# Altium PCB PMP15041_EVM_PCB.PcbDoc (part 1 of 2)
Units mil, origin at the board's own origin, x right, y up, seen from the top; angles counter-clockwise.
Board outline 2200 x 2100 mil, 4 copper layers (Top Layer, Signal Layer 1, Signal Layer 2, Bottom Layer), stack 60 mil thick; 124 components, 58 nets, 320 pads, 164 vias.
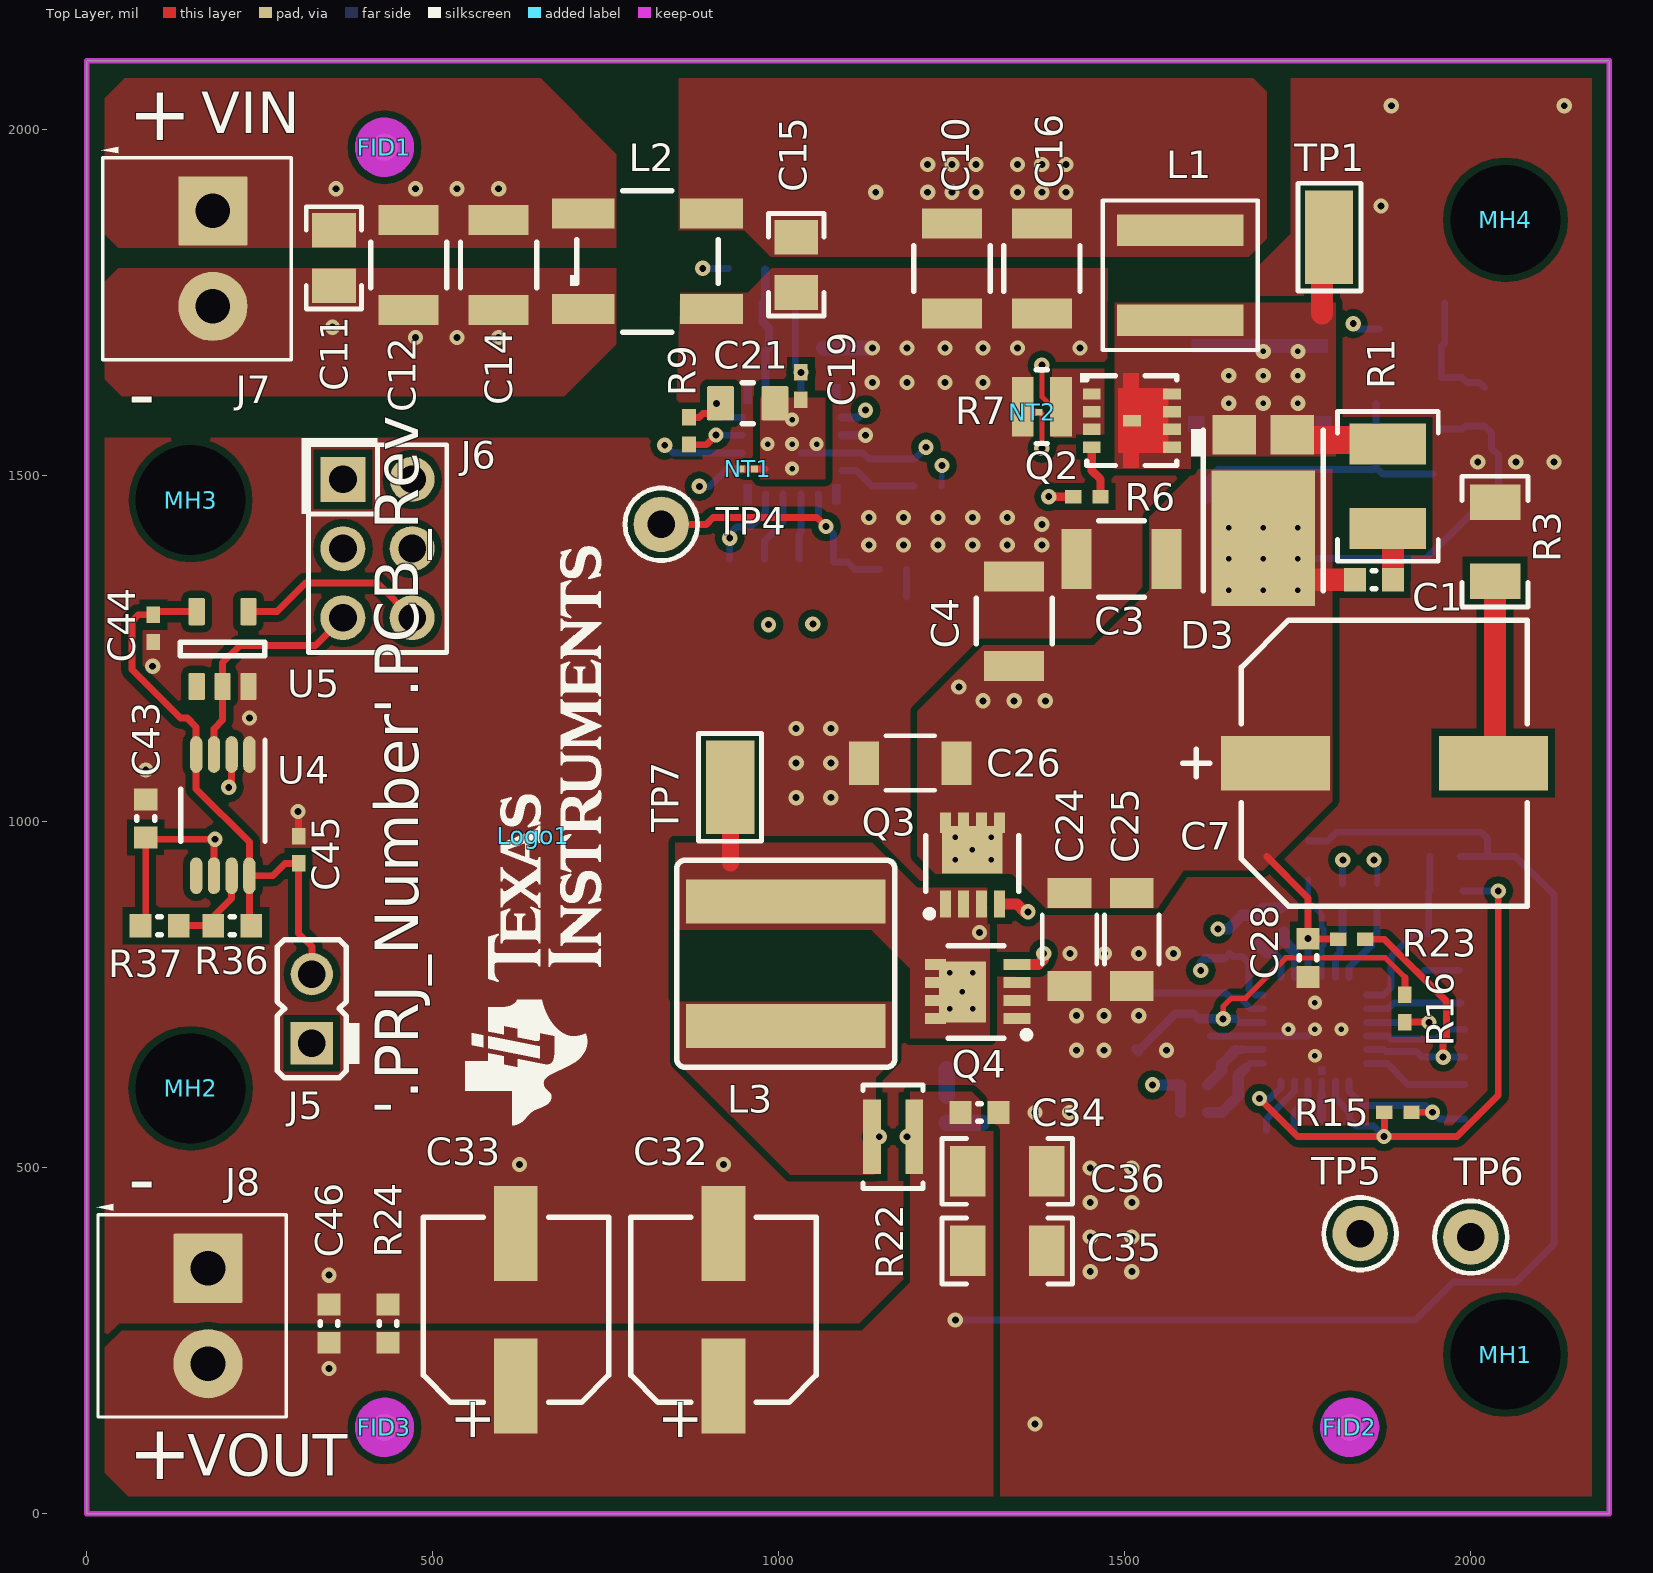
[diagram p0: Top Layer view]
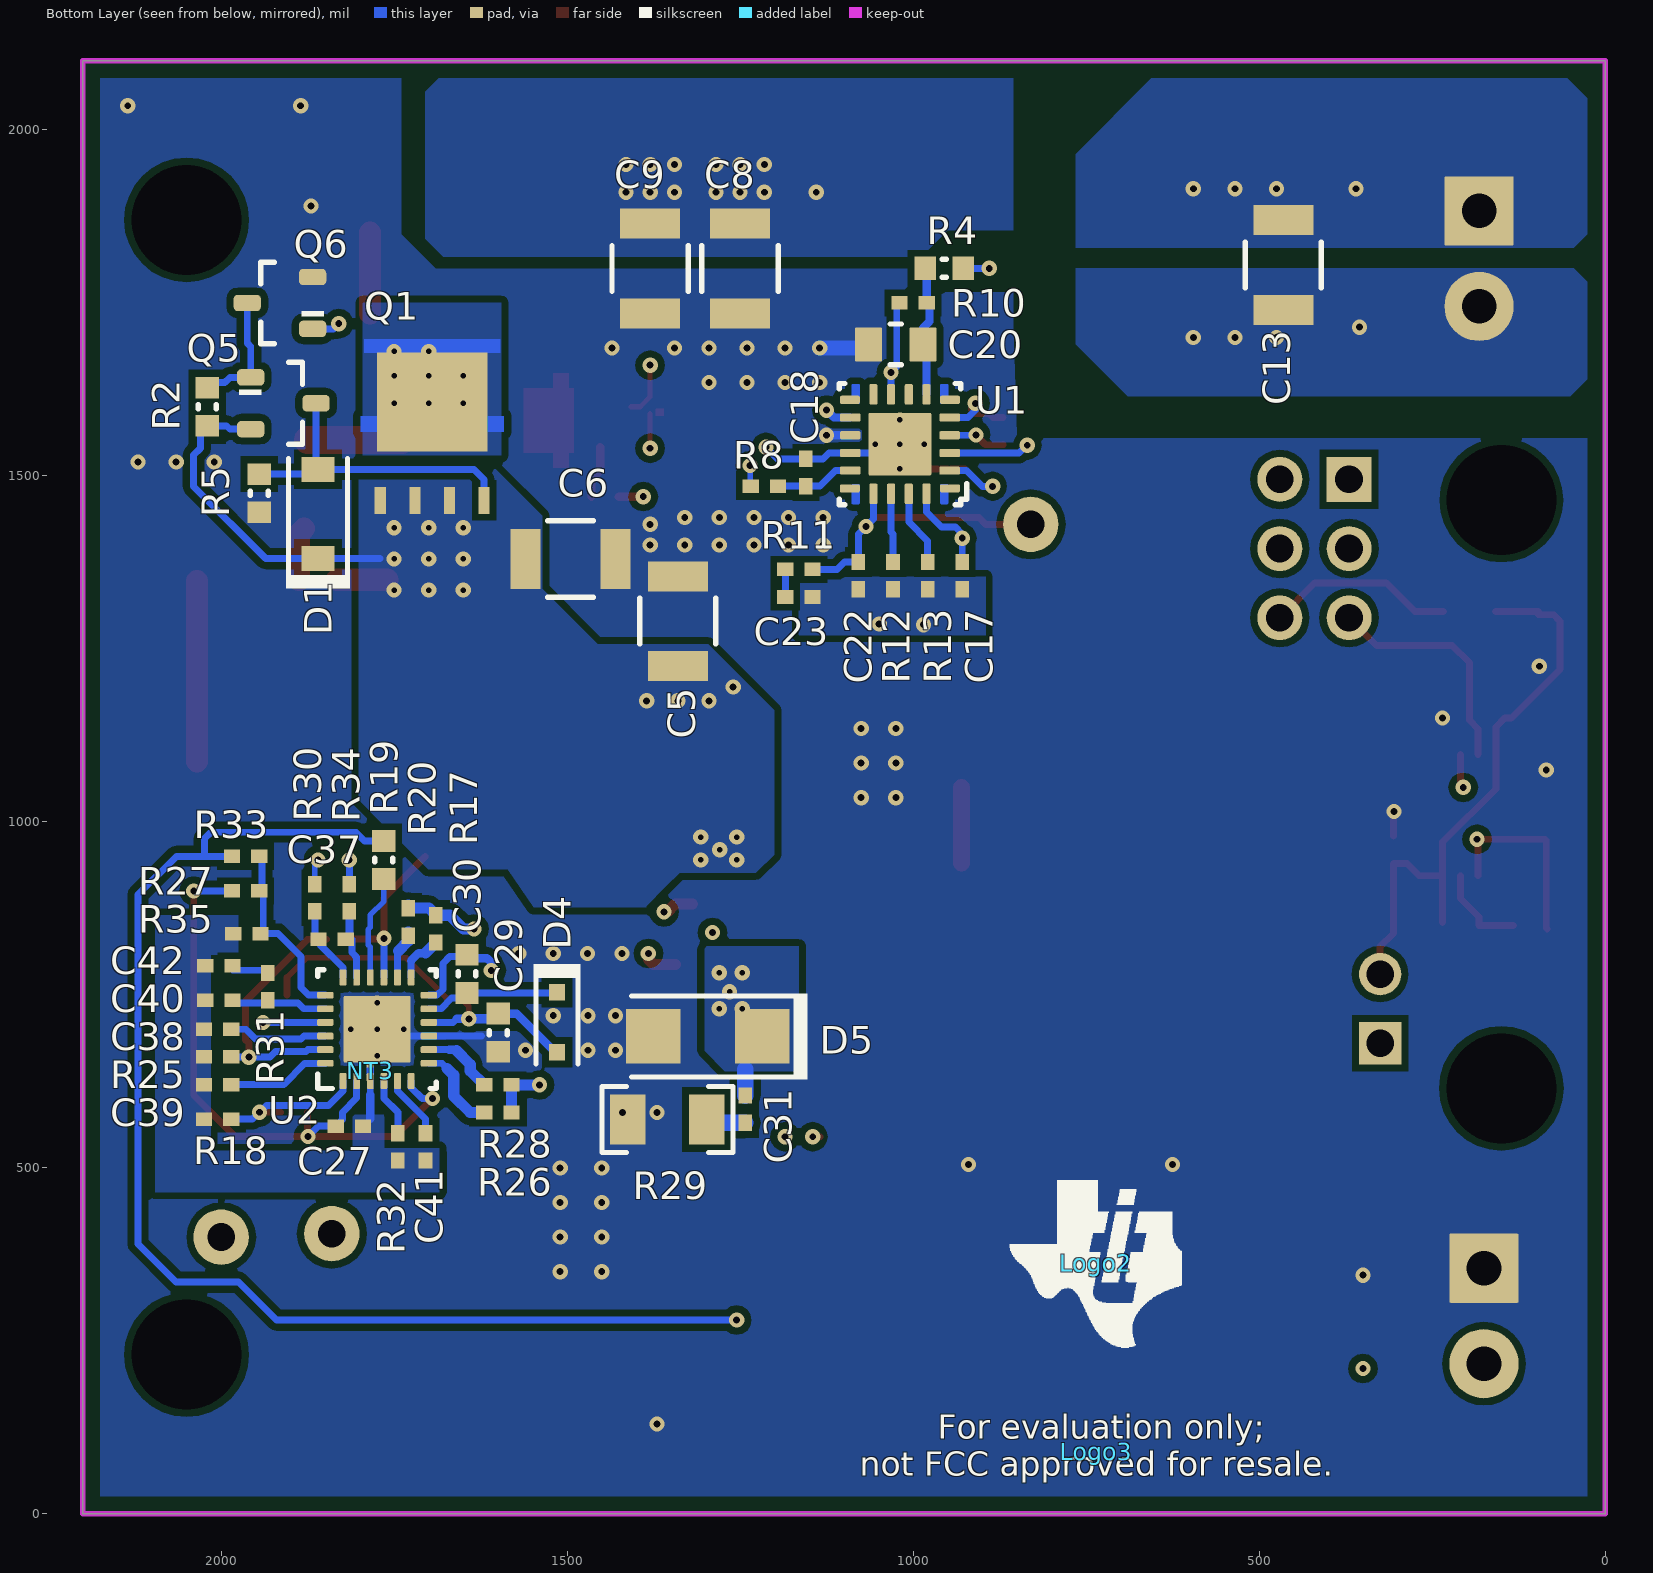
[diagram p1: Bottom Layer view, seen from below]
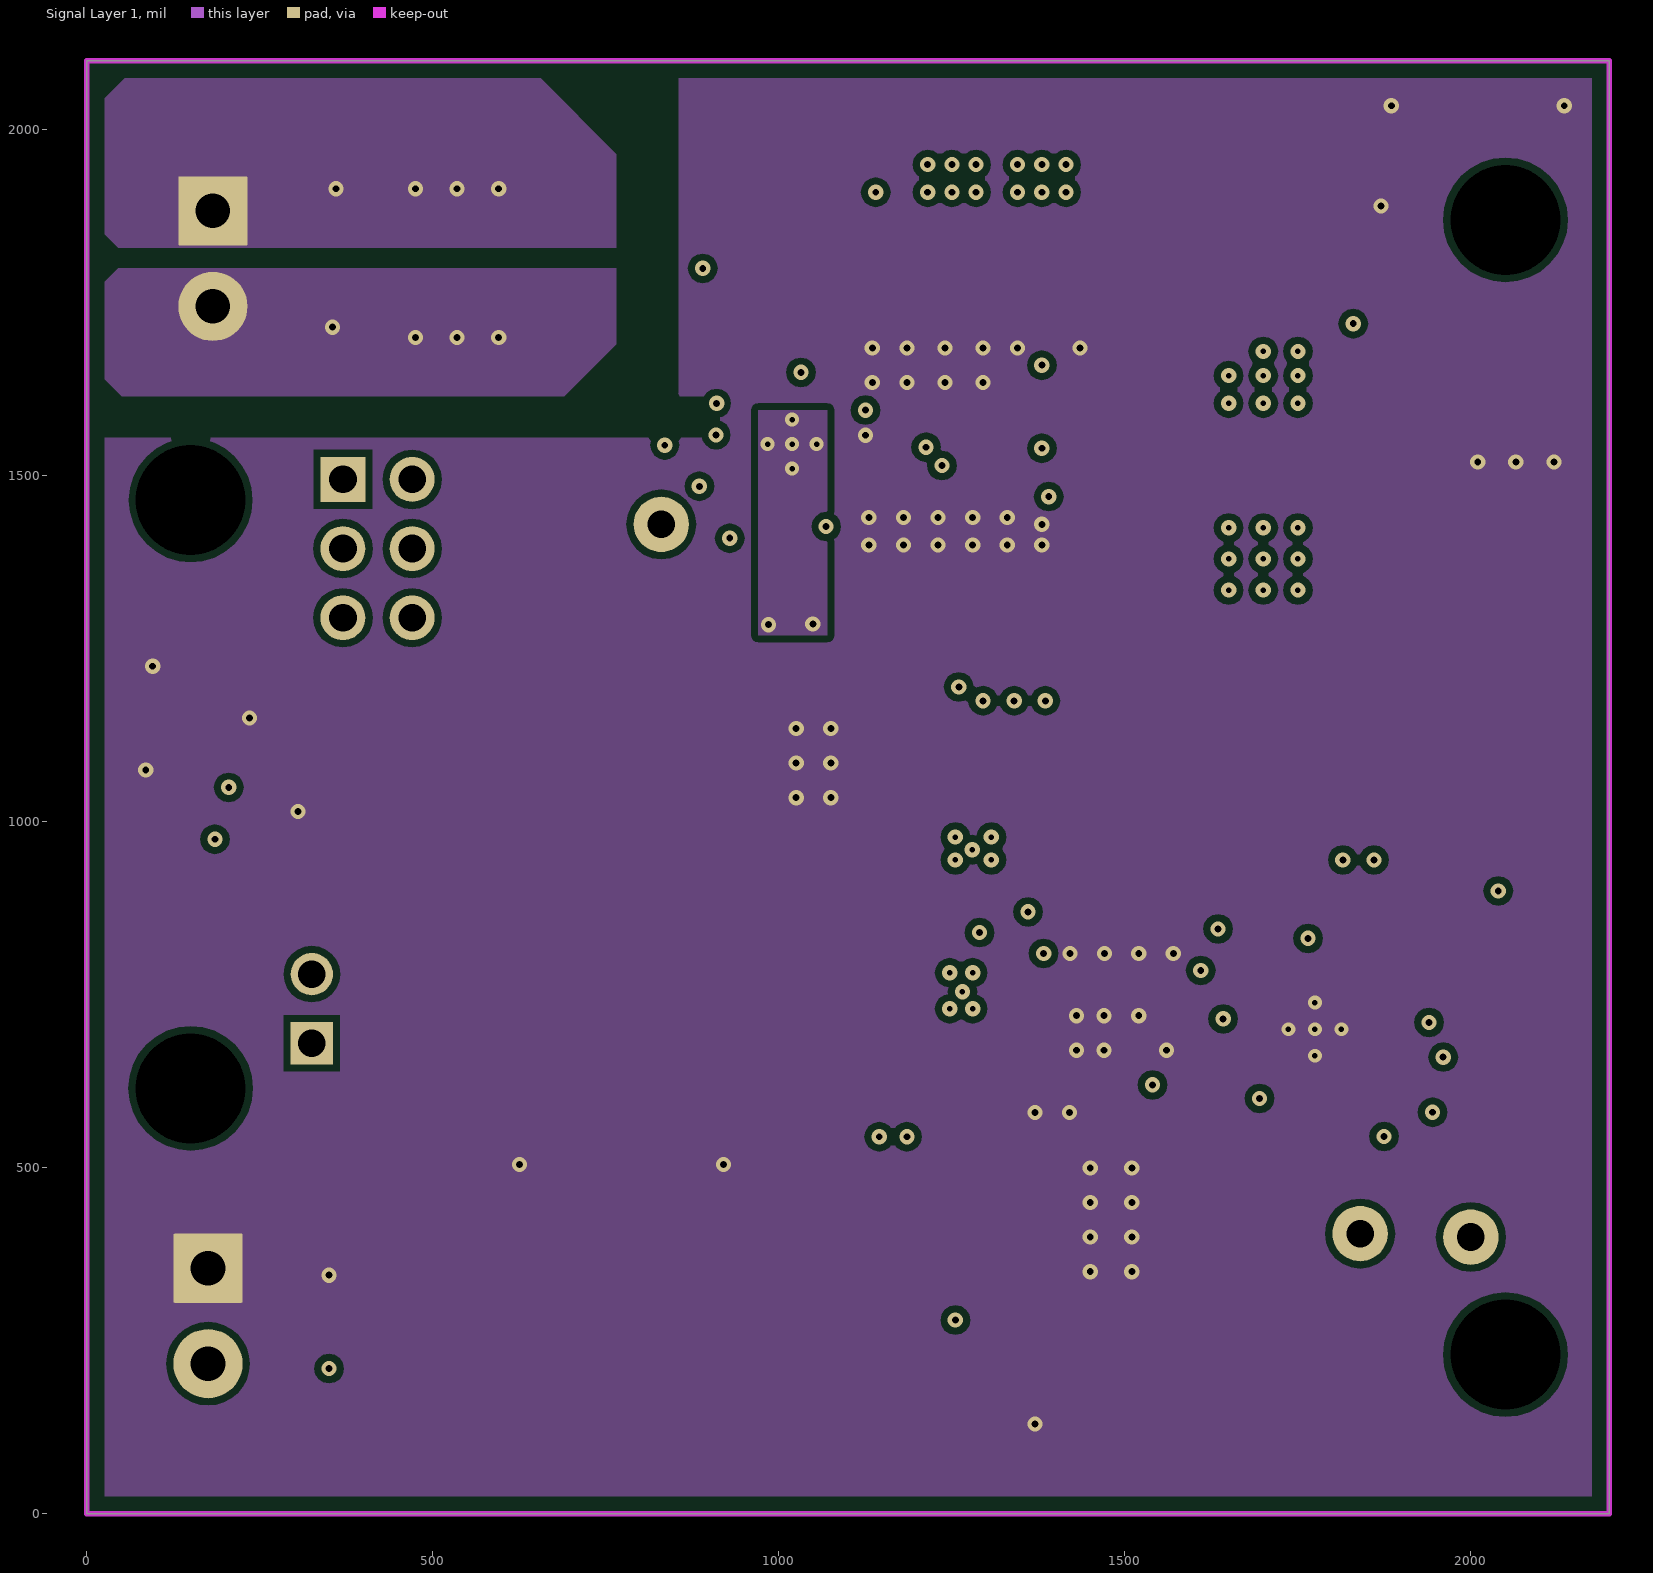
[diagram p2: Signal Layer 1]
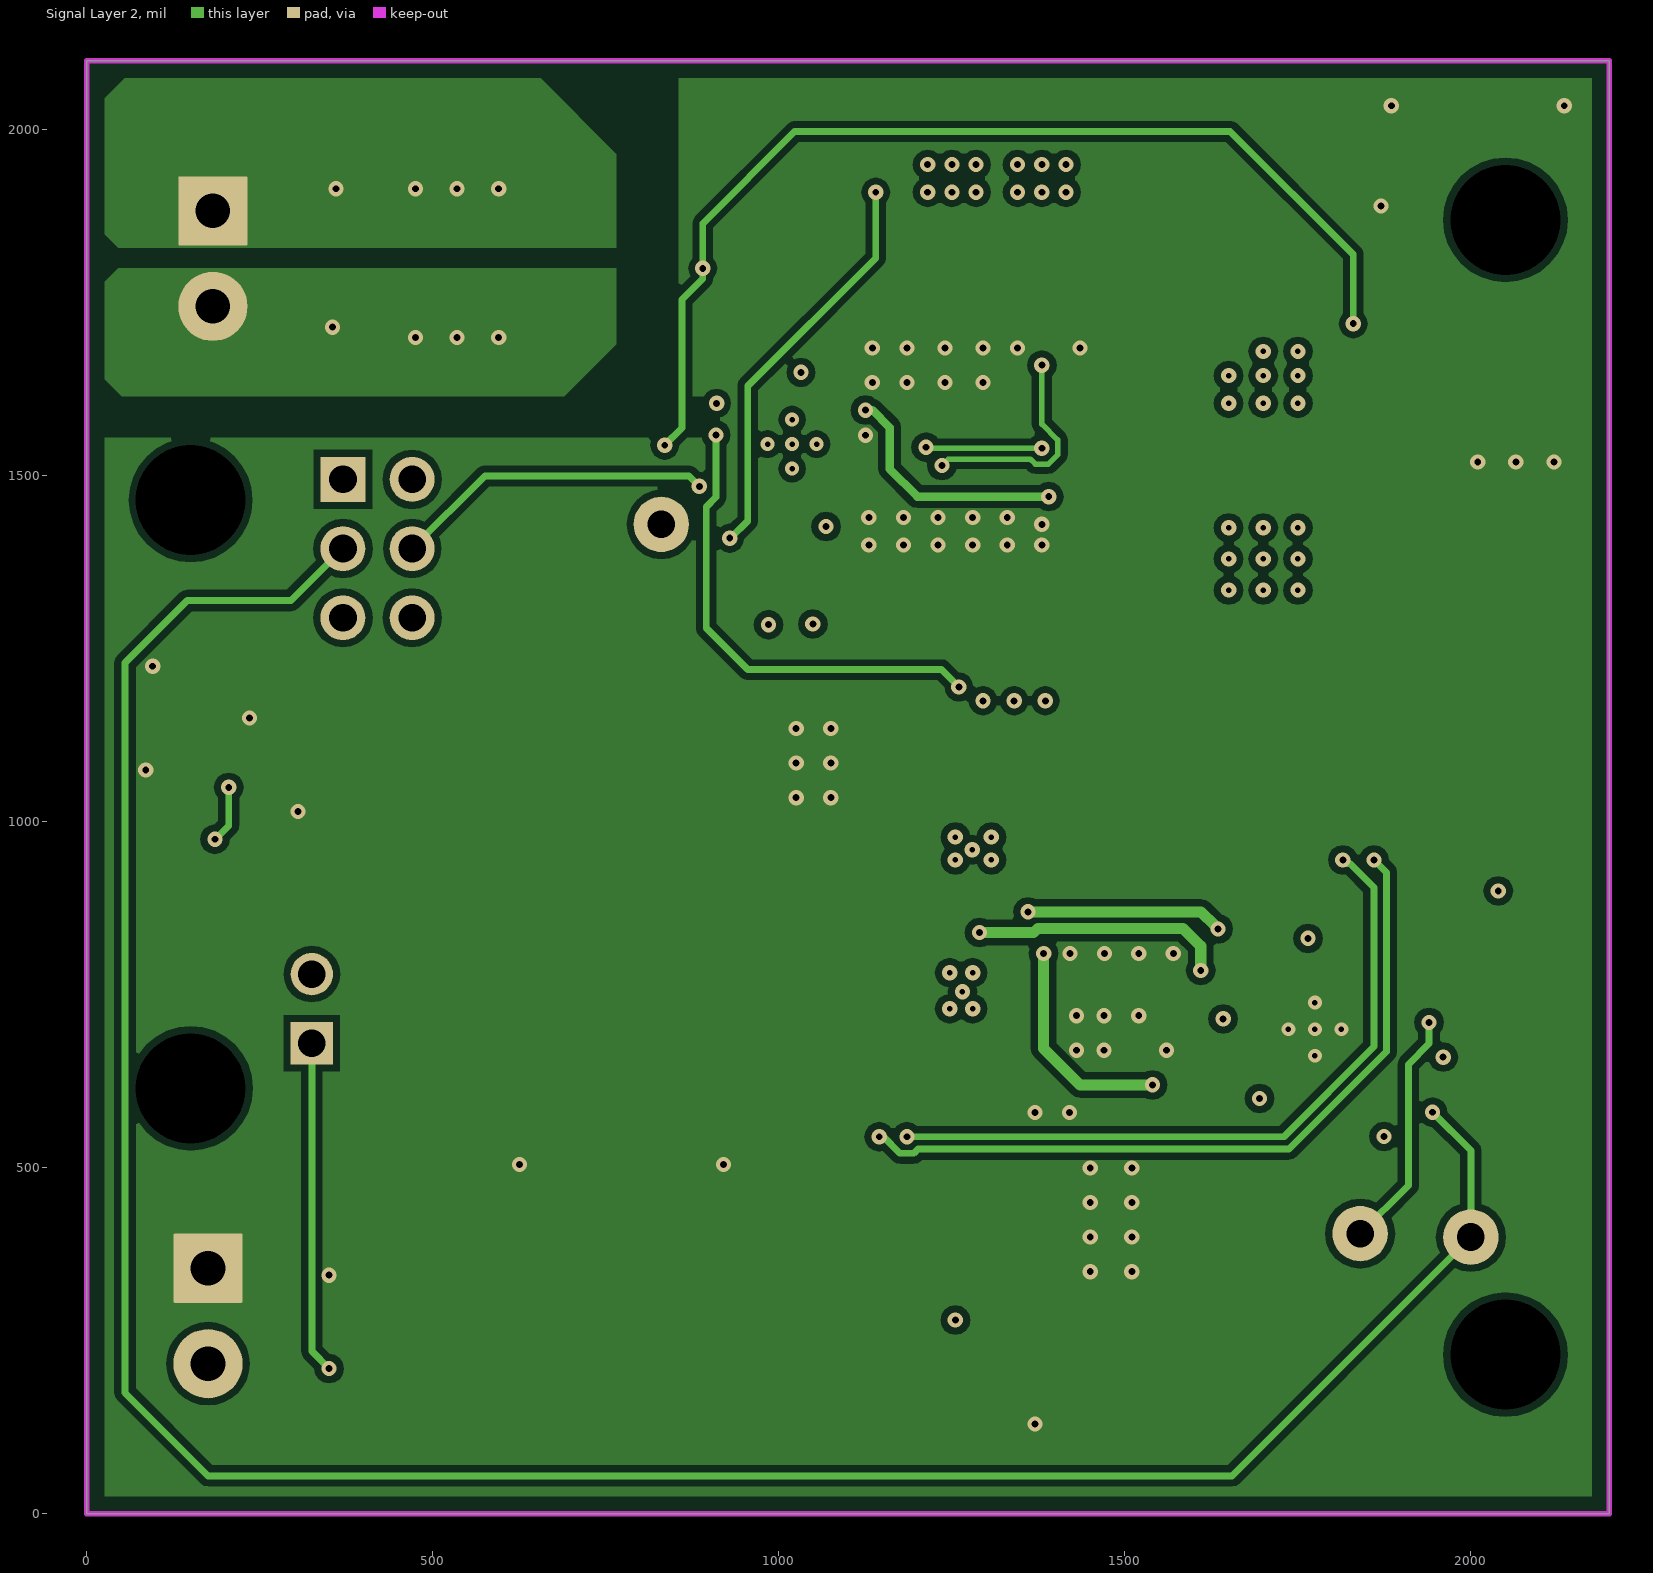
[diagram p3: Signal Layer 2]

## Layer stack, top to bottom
Top Solder: solder mask 0.4, Solder Resist, Dk 3.5
Top Layer: signal copper 2
Dielectric1: core 10, FR-4, Dk 4.8
Signal Layer 1: signal copper 2
Dielectric 2: dielectric 32, Dk 4.2
Signal Layer 2: signal copper 2
Dielectric 3: dielectric 10, Dk 4.2
Bottom Layer: signal copper 2
Bottom Solder: solder mask 0.4, Solder Resist, Dk 3.5

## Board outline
0,0 0,2100 2200,2100 2200,0

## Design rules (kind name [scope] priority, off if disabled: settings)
AcuteAngle [All] p1: minimum=4.50000000000000E+0001 checktracksonly=FALSE
AssemblyTestPointUsage [All] p1: valid=2
BoardOutlineClearance BoardOutlineClearance_MountingHoles [OnCopper and InComponentClass('Mounting Holes')] p1: gap=40 ignorepadtopadclearanceinfootprint=FALSE
BoardOutlineClearance BoardOutlineClearance_Poly [OnCopper and IsPoly] p2: gap=25 ignorepadtopadclearanceinfootprint=FALSE
BoardOutlineClearance [OnCopper and Not InComponentClass('Logo') and not InComponentClass('FiducialMark') and not InRegion(1000,500,4000,800) and not InPoly] p3: gap=50 ignorepadtopadclearanceinfootprint=FALSE
Clearance Clearance_Keepouts [((IsTrack Or IsArc) And Not InPoly) And IsFree and IsKeepOut vs ((IsTrack Or IsArc) And Not InPoly) And IsFree and IsKeepOut] p1: gap=0 ignorepadtopadclearanceinfootprint=FALSE
Clearance Clearance_Poly [InPolygon] p2: gap=10 ignorepadtopadclearanceinfootprint=FALSE
Clearance Clearance_FiducialMark [IsKeepOut and InComponentClass('FiducialMark') vs IsPad and InComponentClass('FiducialMark')] p3: gap=0 ignorepadtopadclearanceinfootprint=FALSE
Clearance [All] p4: gap=7.87 ignorepadtopadclearanceinfootprint=FALSE except(0: Arc-Hole Track-Hole SMDPad-Hole THPad-Hole Via-Hole Fill-Hole Poly-Hole Region-Hole Text-Hole)
ComponentClearance ComponentClearance_NetTie [HasFootprint('Net-Tie_10mil')] p1: gap=0 collisioncheckmode=3 verticalgap=0 showdistances=FALSE
ComponentClearance ComponentClearance_MountingHoles_FiducialMarks [InComponentClass('Mounting Holes') vs InComponentClass('FiducialMark')] p2: gap=50 collisioncheckmode=3 verticalgap=10 showdistances=FALSE
ComponentClearance ComponentClearance_Shunt [InComponentClass('Header') vs InComponentClass('Shunt')] p3: gap=0 collisioncheckmode=3 verticalgap=0 showdistances=FALSE
ComponentClearance ComponentClearance_Logo [InComponentClass('Logo')] p4: gap=20 collisioncheckmode=3 verticalgap=10 showdistances=FALSE
ComponentClearance ComponentClearance_ScrewToNut [(HasFootprint('NY PMS 440 0025 PH')) vs (HasFootprint('Keystone_1902C'))] p5: gap=5 collisioncheckmode=3 verticalgap=10 showdistances=FALSE
ComponentClearance ComponentClearance_MountingHoles [InComponentClass('Mounting Holes')] p6: gap=150 collisioncheckmode=3 verticalgap=100000 showdistances=FALSE
ComponentClearance ComponentClearance_SmallPassives [HasFootprint('0201*') or HasFootprint('0402*') or HasFootprint('0508') or HasFootprint('0603*') or HasFootprint('0612') or HasFootprint('0805*') or HasFootprint('0815*') or HasFootprint('0830*') or HasFootprint('1206*') or HasFootprint('1210*') or HasFootprint('1808*') or HasFootprint('1812*') or HasFootprint('1825*') or HasFootprint('2010*') or HasFootprint('2220*') or HasFootprint('2225*') or HasFootprint('2512*') or HasFootprint('2728*') or HasFootprint('3518*') vs HasFootprint('0201*') or HasFootprint('0402*') or HasFootprint('0508') or HasFootprint('0603*') or HasFootprint('0612') or HasFootprint('0805*') or HasFootprint('0815*') or HasFootprint('0830*') or HasFootprint('1206*') or HasFootprint('1210*') or HasFootprint('1808*') or HasFootprint('1812*') or HasFootprint('1825*') or HasFootprint('2010*') or HasFootprint('2220*') or HasFootprint('2225*') or HasFootprint('2512*') or HasFootprint('2728*') or HasFootprint('3518*')] p7: gap=14.96 collisioncheckmode=3 verticalgap=10 showdistances=FALSE
ComponentClearance ComponentClearance_THtoSMT [IsThruComponent vs IsSMTComponent] p8: gap=30 collisioncheckmode=3 verticalgap=30 showdistances=FALSE
ComponentClearance ComponentClearance_THtoTH [IsThruComponent vs IsThruComponent] p9: gap=30 collisioncheckmode=3 verticalgap=30 showdistances=FALSE
ComponentClearance [All] p10: gap=30 collisioncheckmode=3 verticalgap=10 showdistances=FALSE
DiffPairsRouting [All] p1: maxlimit=100 minlimit=10 mostfreqgap=10 toplayer_minwidth=15 toplayer_maxwidth=15 toplayer_prefwidth=15 midlayer1_minwidth=15 midlayer1_maxwidth=15 midlayer1_prefwidth=15 midlayer2_minwidth=15 midlayer2_maxwidth=15 midlayer2_prefwidth=15 bottomlayer_minwidth=15 bottomlayer_maxwidth=15 bottomlayer_prefwidth=15 maxuncoupledlength=1000
FabricationTestPointUsage TestPointUsage [All] p1: valid=2 allowmultiple=FALSE
FabricationTestpoint Testpoint [All] p1: side=3 testpointundercomponent=TRUE minsize=40 maxsize=100 preferedsize=60 minholesize=0 maxholesize=40 preferedholesize=32 testpointgrid=1 allowsidetop=TRUE allowsidebottom=TRUE usegrid=TRUE gridtolerance=0.01
FanoutControl Fanout_LCC [IsLCC] p1: bgadir=Out bgaviamode=Centered fanoutstyle=Auto fanoutdirection=Alternating viagrid=1 // Fanout_LCC (Default Rule)
FanoutControl Fanout_BGA [IsBGA] p2: bgadir=Out bgaviamode=Centered fanoutstyle=Auto fanoutdirection=Alternating viagrid=1 // Fanout_BGA (Default Rule)
FanoutControl Fanout_Default [All] p4: bgadir=Out bgaviamode=Centered fanoutstyle=Auto fanoutdirection=Alternating viagrid=1 // Fanout_Default (Default Rule)
FanoutControl Fanout_Small [(CompPinCount < 5)] p5: bgadir=Out bgaviamode=Centered fanoutstyle=Auto fanoutdirection=OutThenIn viagrid=1 // Fanout_Small (Default Rule)
HoleSize [All] p1: absolutevalues=TRUE maxlimit=251 minlimit=7.87 maxpercent=80.000 minpercent=20.000
MinimumAnnularRing MinimumAnnularRing_ThermalPadVias [IsVia and InAnyComponent] p1: minimumring=5.91
MinimumAnnularRing [All] p2: minimumring=6
MinimumSolderMaskSliver MinimumSolderMaskSliver_MSOP [HasFootprint('DGK0008A_N')] p1: minsoldermaskwidth=2
MinimumSolderMaskSliver MinimumSolderMaskSliver_Logo [InComponentClass('Logo') vs InComponentClass('Logo')] p2: minsoldermaskwidth=0.7
MinimumSolderMaskSliver [All] p3: minsoldermaskwidth=3.94
PlaneConnect [All] p1: planeconnectstyle=Relief reliefexpansion=10 reliefentries=4 reliefconductorwidth=10 reliefairgap=10
PolygonConnect [All] p1: connectstyle=Direct reliefconductorwidth=10 reliefentries=4 polygonreliefangle="90 Angle" airgapwidth=10
RoutingVias ThermalPadVias [IsVia and InAnyComponent] p1: holewidth=7.87 width=19.68 viastyle="Through Hole" minholewidth=7.87 minwidth=19.68 maxholewidth=12.99 maxwidth=23.62
RoutingVias [All] p2: holewidth=10 width=22 viastyle="Through Hole" minholewidth=7.87 minwidth=20 maxholewidth=40 maxwidth=65
SilkToBoardRegionClearance [Not ((IsComment or IsDesignator) And (Hide <> 'False')) and not InRegion(1000,500,4000,800)] p1:
SilkToSilkClearance SilkToSilkClearance_Pb-FreeLogo [(HasFootprint('Pb-Free_Overlay_Medium') OR HasFootprint('Pb-Free_Overlay_Small')) vs (HasFootprint('Pb-Free_Overlay_Medium') OR HasFootprint('Pb-Free_Overlay_Small'))] p1: silktosilkclearance=0
SilkToSilkClearance [All] p2: silktosilkclearance=4
SilkToSolderMaskClearance SilkToComponentPadClearance [(IsPad or IsFill or IsRegion) and InAnycomponent] p1: minsilkscreentomaskgap=5 clearancetoexposedcopper=TRUE
SilkToSolderMaskClearance "Silk to Solder Mask Opening" [All] p2: minsilkscreentomaskgap=4 clearancetoexposedcopper=FALSE
SolderMaskExpansion [All] p1: expansion=1.97
Width [All] p1: maxlimit=100 minlimit=6 preferedwidth=10 checkconnectedcopper=TRUE
15 further rules are at their usual default settings.

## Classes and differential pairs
component class PMP15041_SYNC_Stage: C43 C44 C45 J5 J6 R36 R37 U4 U5
component class PMP15041_EVM_Buck_Stage: C24 C25 C26 C27 C28 C29 C30 C31 C32 C33 C34 C35 C36 C37 C38 C39 C40 C41 C42 C46 D4 D5 J8 L3 NT3 Q3 Q4 R15 R16 R17 R18 R19 R20 R22 R23 R24 R25 R26 R27 R28 R29 R30 R31 R32 R33 R34 R35 TP5 TP6 TP7 U2 ZX1
component class PMP15041_EVM_Boost_Stage: C1 C3 C4 C5 C6 C7 C8 C9 C10 C11 C12 C13 C14 C15 C16 C17 C18 C19 C20 C21 C22 C23 D1 D3 J7 L1 L2 NT1 NT2 Q1 Q2 Q5 Q6 R1 R2 R3 R4 R5 R6 R7 R8 R9 R10 R11 R12 R13 TP1 TP4 U1
component class Logo: Logo1 Logo2
component class PMP15041_EVM_Hardware: FID1 FID2 FID3 Logo1 Logo2 Logo3 MH1 MH2 MH3 MH4 ZZ1 ZZ2 ZZ3 ZZ4
component class FiducialMark: FID1 FID2 FID3
component class AssemblyNote: ZX1 ZZ1 ZZ2 ZZ3 ZZ4
component class Header: J5 J6

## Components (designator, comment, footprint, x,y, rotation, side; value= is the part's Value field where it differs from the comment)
C1 "GRM188R72A222KA01D" 0603L 1860,1350 r0 top value=2200pF
C3 "CGA6P3X7S1H106K250AB" 1210_280 1495,1380 r180 top value=10uF
C4 "CGA6P3X7S1H106K250AB" 1210_280 1340,1290 r90 top value=10uF
C5 "CGA6P3X7S1H106K250AB" 1210_280 1495,1380 r180 bottom value=10uF
C6 "CGA6P3X7S1H106K250AB" 1210_280 1340,1290 r90 bottom value=10uF
C7 "PCR1H181MCL1GS" CR_1000x1270 1875,1085 r0 top value=180uF
C8 "GRM32ER71H106KA12L" 1210_280 1250,1800 r270 bottom value=10uF
C9 "GRM32ER71H106KA12L" 1210_280 1380,1800 r270 bottom value=10uF
C10 "GRM32ER71H106KA12L" 1210_280 1250,1800 r270 top value=10uF
C11 "C0805C104K1RACTU" 0805_HV 357,1815 r270 top value=0.1uF
C12 "C3225X7R1H106M250AC" 1210_280 465,1805 r270 top value=10uF
C13 "C3225X7R1H106M250AC" 1210_280 465,1805 r270 bottom value=10uF
C14 "C3225X7R1H106M250AC" 1210_280 595,1805 r270 top value=10uF
C15 "C0805C104K1RACTU" 0805_HV 1025,1805 r270 top value=0.1uF
C16 "C3225X7R1H106M250AC" 1210_280 1380,1800 r270 top value=10uF
C17 "CGA2B3X7R1H104M050BB" 0402L 929.02,1355.98 r270 bottom value=0.1uF
C18 "CGA2B2C0G1H102J050BA" 0402L 1155,1505 r90 bottom value=1000pF
C19 "GCM155R71H104KE02D" 0402L 1031.81,1630 r90 top value=0.1uF
C20 "GRM21BR71C475KA73L" 0805_HV1 1025,1690 r0 bottom value=4.7uF
C21 "C2012X7R1H225K125AC" 0805_HV1 955,1605 r180 top value=2.2uF
C22 "GCM155R71H471KA37D" 0402L 1079.02,1355.98 r270 bottom value=470pF
C23 "CGA2B3X7R1H333K050BB" 0402L 1165,1325 r180 bottom value=0.033uF
C24 "CL31B225KCHSNNE" 1206_190 1420,830 r270 top value=2.2uF
C25 "CL31B225KCHSNNE" 1206_190 1510,830 r270 top value=2.2uF
C26 "CL31B225KCHSNNE" 1206_190 1190,1085 r180 top value=2.2uF
C27 "GCM155R71H104KE02D" 0402L 1814.61,560.39 r0 bottom value=0.1uF
C28 "CGA3E3X7R1H474M080AE" 0603L 1764.76,803.46 r90 top value=0.47uF
C29 "GRM188R61C475KAAJ" 0603L 1599.61,695.39 r90 bottom value=4.7uF
C30 "C0603C104K5RACTU" 0603L 1644.61,780.39 r90 bottom value=0.1uF
C31 "GRM155R72A102KA01D" 0402L 1242.76,585 r270 bottom value=1000pF
C32 "875105344009" WCAP-PSLP_630x580 920,295 r90 top value=82uF
C33 "875105344009" WCAP-PSLP_630x580 620,295 r90 top value=82uF
C34 "C0603C104K5RACTU" 0603L 1290,580 r0 top value=0.1uF
C35 "C3216X5R1C476M160AB" 1206 1330,380 r0 top value=47uF
C36 "C3216X5R1C476M160AB" 1206 1330,495 r0 top value=47uF
C37 "C0402C330J5GAC" 0402L 1839.61,830.37 r0 bottom value=33pF
C38 "C1005X7R1H683K050BB" 0402L 2005.11,700.39 r0 bottom value=0.068uF
C39 "CGA2B3X7R1H103K050BB" 0402L 2005.11,620.39 r0 bottom value=0.01uF
C40 "GCM1555C1H220JA16D" 0402L 2003.3,742.05 r0 bottom value=22pF
C41 "CGA2B3X7R1H103K050BB" 0402L 1704.61,530.39 r270 bottom value=0.01uF
C42 "CGA2B3X7R1H103K050BB" 0402L 2003.3,792.05 r0 bottom value=0.01uF
C43 "885012006057" 0603L 85,1004.94 r90 top value=100pF
C44 "GCM155R71H104KE02D" 0402L 95.99,1279.72 r90 top value=0.1uF
C45 "GCM155R71H104KE02D" 0402L 305.99,959.72 r270 top value=0.1uF
C46 "C0603C104K5RACTU" 0603L 350,275 r90 top value=0.1uF
D1 "DDZ16Q-7" SOD-123 1860,1445 r90 bottom value=16V
D3 "PMEG060V100EPDZ" SOT1289 1700,1450 r0 top value=60V
D4 "PMEG6010CEJ,115" SOD-323F 1514.61,710.39 r270 bottom value=60V
D5 "B170-13-F" SMA 1296.81,689.96 r0 bottom value=70V
FID1 "Fiducial" Fiducial10-20 430,1975 r0 top
FID2 "Fiducial" Fiducial10-20 1825,125 r0 top
FID3 "Fiducial" Fiducial10-20 430,125 r0 top
J5 "GBC02SAAN" Sullins_Gxx02SAAN 325,730 r90 top
J6 "PEC03DAAN" SULLINS_PEC03DAAN 420,1395 r270 top
J7 "ED555/2DS" TERM_BLK_ED555-2DS 182,1883 r270 top
J8 "ED555/2DS" TERM_BLK_ED555-2DS 175,355 r270 top
L1 "XAL5030-331MEB" XAL5030 1580,1790 r270 top value=330nH
L2 "PLT5BPH5013R1SNL" PLT5BPH_SN 810,1810 r90 top
L3 "XAL7070-182MEB" XAL7070 1010,795 r270 top value=1.8uH
Logo1 "Texas Instruments" TI_Stacked_Overlay_Small 645,980 r90 top
Logo2 "Texas Instruments" TI_Symbol_Overlay_Medium 735.91,361.92 r180 bottom
Logo3 "FCC disclaimer" FCC_disclaimer_stacked 735,90 r180 bottom
MH1 "MTG_NoPads" MTG_159mil 2050,230 r0 top
MH2 "MTG_NoPads" MTG_159mil 150,615 r0 top
MH3 "MTG_NoPads" MTG_159mil 150,1465 r0 top
MH4 "MTG_NoPads" MTG_159mil 2050,1870 r0 top
NT1 "Net-Tie" Net-Tie_10mil 955,1510 r180 top net-tie
NT2 "Net-Tie" Net-Tie_10mil 1366,1592 r180 top net-tie
NT3 "Net-Tie" Net-Tie_10mil 1784.61,640.39 r90 bottom net-tie
Q1 "SQJ461EP" PowerPAK_SO-8L 1695,1575 r90 bottom value=-60V
Q2 "NVTFS5C670NLTAG" Power_WDFN-8 1510,1580 r0 top
Q3 "SQ7414AEN-T1-GE3" PowerPAK_1212-8_NoVias 1280,940 r90 top
Q4 "SQ7414AEN-T1-GE3" PowerPAK_1212-8_NoVias 1285,755 r180 top
Q5 "SI2309CDS-T1-E3" SOT-23 1910,1605 r180 bottom value=-60V
Q6 "MMBTA05LT1G" SOT-23 1915,1750 r0 bottom value="60 V"
R1 "ERJ-14BQF2R0U" 1210M 1880,1485 r270 top value=2.00
R2 "CRCW060320K0FKEA" 0603L 2020,1600 r270 bottom value=20.0k
R3 "ERJ-8RSJR18V" 1206 2035,1405 r270 top value=0.18
R4 "CRCW060349K9FKEA" 0603L 955,1800 r0 bottom value=49.9k
R5 "CRCW0603100KFKEA" 0603L 1945,1475 r90 bottom value=100k
R6 "CRCW04021R00FKED" 0402L 1445,1470 r180 top value=1.00
R7 "KRL2012M-R005-F-T1" KRL2012 1380,1600 r0 top value=0.005
R8 "CRCW040249R9FKED" 0402L 1215,1485 r0 bottom value=49.9
R9 "MCR01MZPJ000" 0402L 870,1565 r90 top value=0
R10 "RMCF0402JT10R0" 0402L 1000,1750 r180 bottom value=10.0
R11 "CRCW04024K64FKED" 0402L 1165,1365 r180 bottom value=4.64k
R12 "CRCW04029K53FKED" 0402L 1029.02,1355.98 r90 bottom value=9.53k
R13 "CRCW040229K4FKED" 0402L 979.02,1355.98 r90 bottom value=29.4k
R15 "MCR01MZPJ000" 0402L 1894.61,580.39 r180 top value=0
R16 "ERJ-2GEJ103X" 0402L 1904.61,730.39 r270 top value=10k
R17 "CRCW040210R0JNED" 0402L 1689.61,845.39 r90 bottom value=10
R18 "MCR01MZPJ000" 0402L 2005.11,570.39 r0 bottom value=0
R19 "CRCW06030000Z0EA" 0603L 1765,945 r90 bottom value=0
R20 "RK73Z1ETTP" 0402L 1729.61,855.39 r270 bottom value=0
R22 "PRL1632-R010-F-T1" 0612 1165,545 r0 top value=0.01
R23 "MCR01MZPJ000" 0402L 1827.8,830.37 r0 top value=0
R24 "CRCW0603100KFKEA" 0603L 435,275 r270 top value=100k
R25 "MCR01MZPJ000" 0402L 2005.11,660.39 r180 bottom value=0
R26 "RK73Z1ETTP" 0402L 1600,580 r180 bottom value=0
R27 "RK73Z1ETTP" 0402L 1964.61,900.39 r180 bottom value=0
R28 "RK73Z1ETTP" 0402L 1600,620 r0 bottom value=0
R29 "CRM1206-JW-1R0ELF" 1206 1355,570 r180 bottom value=1.0
R30 "RK73Z1ETTP" 0402L 1864.61,890.39 r90 bottom value=0
R31 "CRCW040210K2FKED" 0402L 1932.8,762.05 r270 bottom value=10.2k
R32 "ERJ-2RKF4992X" 0402L 1744.61,530.39 r90 bottom value=49.9k
R33 "RK73Z1ETTP" 0402L 1964.61,950.24 r180 bottom value=0
R34 "RK73Z1ETTP" 0402L 1814.61,890.39 r90 bottom value=0
R35 "0" 0402L 1962.8,838.43 r0 bottom
R36 "RC0603FR-072K2L" 0603L 210,850 r0 top value=2.20k
R37 "RC0603FR-072K2L" 0603L 105,850 r0 top value=2.20k
TP1 "5015" Testpoint_Keystone_Miniature 1795,1845 r90 top
TP4 "5002" Keystone5002 830,1430 r180 top
TP5 "5002" Keystone5002 1840,405 r180 top value=White
TP6 "5002" Keystone5002 2000,400 r180 top value=White
TP7 "5015" Testpoint_Keystone_Miniature 930,1050 r270 top
U1 "LM5150QRUMRQ1" RUM0016C 1019.02,1545.98 r0 bottom
U2 "LM5141QRGERQ1" RGE0024J 1774.61,700.39 r90 bottom
U4 "LMC555CMMX" DGK0008A_N 196.31,1009.72 r270 top
U5 "SN74LVC1G04DBVR" DBV0005A_N 195.99,1249.72 r90 top
ZX1 "Fsw = 2.2MHz" AssemblyNote 14488,926 r90 top
ZZ1 "This Assembly Note is for PCB labels only" AssemblyNoteLabel 185,3938 r0 top
ZZ2 "These assemblies are ESD sensitive, ESD precautions shall be observed." AssemblyNote 185,3829.11 r0 top
ZZ3 "These assemblies must be clean and free from flux and all contaminants. Use of no clean flux is not acceptable." AssemblyNote 185,3740.56 r0 top
ZZ4 "These assemblies must comply with workmanship standards IPC-A-610 Class 2, unless otherwise specified." AssemblyNote 185,3652 r0 top

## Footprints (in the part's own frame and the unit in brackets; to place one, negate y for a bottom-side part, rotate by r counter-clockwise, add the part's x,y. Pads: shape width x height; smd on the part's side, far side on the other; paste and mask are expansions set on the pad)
0402L [mm] "0402 from SM-752 data"
  rect 0.6x0.5 smd: 1(-0.5,0) 2(0.5,0)
  body extent -0.55,-0.3 0.55,0.3, height 0.6
0603L [mm] "0603 from SM-752 data"
  rect 0.8x0.85 smd: 1(-0.7,0) 2(0.7,0)
  silkscreen extent -0.07,-0.33 0.07,0.33, body extent -0.87,-0.47 0.87,0.47, height 1
0612 [mm] "Panasonic recommended land pattern, fb97d03ed01.pdf dated April 2008"
  rect 0.65x2.75 smd: 1(-0.775,0) 2(0.775,0)
  silkscreen extent -1.1,-1.9 1.1,1.9, body extent -0.9,-1.7 0.9,1.7, height 0.85
0805_HV [mil] "0805 with 30mil clearance between pads"
  rect 50x63 smd: 1(-40,0) 2(40,0)
  silkscreen extent -74,-40 74,40, body extent -43,-29 43,29, height 57
0805_HV1 [mm] "Custom footprint based on analyzing multiple manufacturer recommendations"
  rrect10% 1x1.25 smd: 1(-1,0) 2(1,0)
  silkscreen extent -0.2,-0.75 0.2,0.75, body extent -1.1,-0.72 1.1,0.73, height 1.45
1206 [mm] "1206 from SM-752 data"
  rect 1.3x1.85 smd: 1(-1.45,0) 2(1.45,0)
  silkscreen extent -2.4,-1.21 2.4,1.21, body extent -1.7,-0.9 1.7,0.9, height 1.35
1206_190 [mm] "1206_190"
  rect 1.1x1.6 smd: 1(-1.7,0) 2(1.7,0)
  silkscreen extent -0.9,-1 0.9,1, body extent -1.75,-0.95 1.75,0.95, height 1.9
1210_280 [mm] "SMD, 2-Leads, Body 3.6x2.8mm, Height 2.8mm"
  rect 1.1x2.2 smd: 1(-1.65,0) 2(1.65,0)
  silkscreen extent -0.84,-1.4 0.84,1.4, body extent -1.8,-1.4 1.8,1.4, height 2.8
1210M [mm] "1210 from SM-752 data"
  rect 1.5x2.8 smd: 1(-1.55,0) 2(1.55,0)
  silkscreen extent -2.75,-1.85 2.75,1.85, body extent -1.7,-1.35 1.7,1.35, height 1.35
AssemblyNote [mil] "Assembly Note"
AssemblyNoteLabel [mil] "Assembly Note for PCB Labels"
CR_1000x1270 [mm] "SMD, 2-Leads, Dia 10.5mm, Pin Spacing 8mm"
  rect 4x2 smd: 1(-4,0) 2(4,0)
  silkscreen extent -7.4,-5.25 5.25,5.25, body extent -5.25,-5.25 5.25,5.25, height 12.71
DBV0005A_N [mm] "SOT23, 5-Leads, Body 2.9x1.6mm, Pitch 0.95mm, Lead Span 2.8mm, IPC Medium Density"
  rrect17% 1x0.6 smd: 1(-1.375,0.95) 2(-1.375,0) 3(-1.375,-0.95) 4(1.375,-0.95) 5(1.375,0.95)
  silkscreen extent -0.25,-1.55 0.25,1.55, body extent -1.42,-1.46 1.42,1.46, height 1.09
DGK0008A_N [mm] "TSOP, 8-Leads, Body 3x3mm, Pitch 0.65mm, IPC Medium Density"
  oval 1.35x0.45 smd: 1(-2.225,0.975) 2(-2.225,0.325) 3(-2.225,-0.325) 4(-2.225,-0.975) 5(2.225,-0.975) 6(2.225,-0.325) 7(2.225,0.325) 8(2.225,0.975)
  silkscreen extent -2.75,-1.55 0.95,1.55, body extent -2.45,-1.5 2.45,1.5, height 0.96
FCC_disclaimer_stacked [mil]
Fiducial10-20 [mm]
  round 1 smd mask+0.5: 1(0,0)
  Top Layer keep-out circle w1.178: c0,0 r0.5
Keystone5002 [mil] "For Keystone 500x miniature loop terminals"
  round 80 hole 40: 1(0,0)
  silkscreen extent -52,-52 52,52, body extent -49,-49 49,49, height 182
KRL2012 [mm] "SUSUMU"
  rect 0.8x2.2 smd: 1(-0.7,0) 2(0.7,0)
  silkscreen extent -0.2,-1.35 0.2,1.35, body extent -0.72,-1.1 0.72,1.1, height 0.7
MTG_159mil [mil] "159mil Non Plated Hole"
  round 150 hole 159 unplated: 1(0,0)
Net-Tie_10mil [mil] "10mil net tie, no solder mask opening, no solder paste"
  rect 10x10 smd paste-5 mask-5: 1(-10,0) 2(10,0)
  Top Layer region: -6,5 6,5 6,-5 -6,-5
PLT5BPH_SN [mm] "SMD, 4-Leads, Body 5x5mm"
  rect 1.1x2.3 smd: 1(-1.75,2.35) 2(-1.75,-2.35) 3(1.75,-2.35) 4(1.75,2.35)
  silkscreen extent -2.6,-2.6 2.6,2.85, body extent -2.6,-3.15 2.6,3.15, height 5
Power_WDFN-8 [mm] "SMD, 8-Leads, Body 3.3x3.3mm, Pitch 0.65mm"
  rect 0.66x0.42 smd: 1(-1.47,0.975) 2(-1.47,0.325) 3(-1.47,-0.325) 4(-1.47,-0.975) 5(1.47,-0.975) 6(1.47,-0.325) 7(1.47,0.325) 8(1.47,0.975) 9(0,0)
  Top Layer region: 0.25,1.73 -0.32,1.73 -0.32,1.185 -0.5,1.185 -0.5,-1.185 -0.32,-1.185 -0.32,-1.73 0.25,-1.73 0.25,-1.185 1.33,-1.185 1.33,1.185 0.25,1.185
  silkscreen extent -1.9,-1.65 1.65,1.75, body extent -1.65,-1.65 1.65,1.65, height 0.81
PowerPAK_1212-8_NoVias [mil] "Vishay PowerPAK 1212-8, Body 3.4x3.2mm (max), Pitch 0.65mm, IPC Medium Density"
  rect 39x16 smd mask+2.01: 1(-58.75,39) 2(-58.75,13) 3(-58.75,-13) 4(-58.75,-39)
  rect 30x16 smd mask+2.01: 5(58.75,-39) 6(58.75,-13) 7(58.75,13) 8(58.75,39)
  rect 68x88 smd mask+2.01: 9(19.75,0.61)
  silkscreen extent -78,-66 40,68, body extent -65,-65 65,65, height 43
PowerPAK_SO-8L [mm] "based on Vishay recommended land pattern Document 63818 Feb 7, 2012"
  rect 1x0.41 smd: 1(-2.805,1.905) 2(-2.805,0.635) 3(-2.805,-0.635) 4(-2.805,-1.905)
  rect 3.63x4.061 smd: 5(0.805,0)
  Top Layer region: 2.615,2.5 3.125,2.5 3.125,-2.5 2.615,-2.5
  Top Layer region: -0.297,2.64 0.297,2.64 0.297,2.03 -0.297,2.03
  Top Layer region: -0.297,-2.03 0.297,-2.03 0.297,-2.64 -0.297,-2.64
  body extent -3.07,-2.57 3.07,2.57, height 1.21
RGE0024J [mm] "QFN, 24-Leads, Body 4x4mm, Pitch 0.5mm, Thermal Pad 2.45x2.45mm, TI Recommended"
  rrect40% 0.6x0.25 smd: 1(-1.9,1.25) 2(-1.9,0.75) 3(-1.9,0.25) 4(-1.9,-0.25) 5(-1.9,-0.75) 6(-1.9,-1.25) 13(1.9,-1.25) 14(1.9,-0.75) 15(1.9,-0.25) 16(1.9,0.25) 17(1.9,0.75) 18(1.9,1.25)
  rrect40% 0.25x0.6 smd: 7(-1.25,-1.9) 8(-0.75,-1.9) 9(-0.25,-1.9) 10(0.25,-1.9) 11(0.75,-1.9) 12(1.25,-1.9) 19(1.25,1.9) 20(0.75,1.9) 21(0.25,1.9) 22(-0.25,1.9) 23(-0.75,1.9) 24(-1.25,1.9)
  rrect9% 1.08x1.08 on Bottom Paste: 25(-0.64,-0.64) 25(-0.64,0.64) 25(0.64,-0.64) 25(0.64,0.64)
  rrect4% 2.45x2.45 smd paste-1.225: 25(0,0)
  silkscreen extent -2.17,-2.17 2.17,2.17, body extent -2,-2 2,2, height 1
RUM0016C [mm] "QFN, 16-Leads, Body 4x4mm, Pitch 0.65mm, Thermal Pad 2.3x2.3mm, TI Recommended"
  rrect33% 0.75x0.3 smd: 1(-1.825,0.975) 2(-1.825,0.325) 3(-1.825,-0.325) 4(-1.825,-0.975) 9(1.825,-0.975) 10(1.825,-0.325) 11(1.825,0.325) 12(1.825,0.975)
  rrect33% 0.3x0.75 smd: 5(-0.975,-1.825) 6(-0.325,-1.825) 7(0.325,-1.825) 8(0.975,-1.825) 13(0.975,1.825) 14(0.325,1.825) 15(-0.325,1.825) 16(-0.975,1.825)
  rrect10% 1.02x1.02 on Bottom Paste: 17(-0.61,-0.61) 17(-0.61,0.61) 17(0.61,-0.61) 17(0.61,0.61)
  rrect4% 2.3x2.3 smd paste-1.35: 17(0,0)
  rrect36% 0.725x0.275 on Bottom Paste: A1(-1.837,1.613) A2(-1.837,-1.613) A3(1.837,-1.613) A4(1.837,1.613)
  rrect33% 0.725x0.3 smd paste-0.15: A1(-1.837,1.625) A2(-1.837,-1.625) A3(1.837,-1.625) A4(1.837,1.625)
  rrect36% 0.275x0.725 on Bottom Paste: A1(-1.613,1.837) A2(-1.613,-1.837) A3(1.613,-1.837) A4(1.613,1.837)
  Top Layer region: -1.775,1.525 -1.775,2.15 -1.771,2.169 -1.76,2.185 -1.744,2.196 -1.725,2.2 -1.725,2.2 -1.525,2.2 -1.506,2.196 -1.49,2.185 -1.479,2.169 -1.475,2.15 -1.475,2.15 -1.475,1.525 -1.479,1.506 -1.49,1.49 -1.506,1.479 -1.525,1.475 -1.525,1.475 -1.725,1.475 -1.744,1.479 -1.76,1.49 -1.771,1.506 -1.775,1.525
  Top Layer region: -1.775,-1.525 -1.775,-2.15 -1.771,-2.169 -1.76,-2.185 -1.744,-2.196 -1.725,-2.2 -1.725,-2.2 -1.525,-2.2 -1.506,-2.196 -1.49,-2.185 -1.479,-2.169 -1.475,-2.15 -1.475,-2.15 -1.475,-1.525 -1.479,-1.506 -1.49,-1.49 -1.506,-1.479 -1.525,-1.475 -1.525,-1.475 -1.725,-1.475 -1.744,-1.479 -1.76,-1.49 -1.771,-1.506 -1.775,-1.525
  Top Layer region: 1.775,-1.525 1.775,-2.15 1.771,-2.169 1.76,-2.185 1.744,-2.196 1.725,-2.2 1.725,-2.2 1.525,-2.2 1.506,-2.196 1.49,-2.185 1.479,-2.169 1.475,-2.15 1.475,-2.15 1.475,-1.525 1.479,-1.506 1.49,-1.49 1.506,-1.479 1.525,-1.475 1.525,-1.475 1.725,-1.475 1.744,-1.479 1.76,-1.49 1.771,-1.506 1.775,-1.525
  Top Layer region: 1.775,1.525 1.775,2.15 1.771,2.169 1.76,2.185 1.744,2.196 1.725,2.2 1.725,2.2 1.525,2.2 1.506,2.196 1.49,2.185 1.479,2.169 1.475,2.15 1.475,2.15 1.475,1.525 1.479,1.506 1.49,1.49 1.506,1.479 1.525,1.475 1.525,1.475 1.725,1.475 1.744,1.479 1.76,1.49 1.771,1.506 1.775,1.525
  silkscreen extent -2.45,-2.23 2.23,2.22, body extent -2,-2 2,2, height 0.8
SMA [mm] "Molded Diode, 2-Leads, Body 4.3x2.6mm, IPC Medium Density, based on OnSemi component dimensions and land pattern"
  rect 2x2 smd: 1(-2,0) 2(2,0)
  silkscreen extent -3.66,-1.57 2.79,1.57, body extent -2.6,-1.3 2.6,1.3, height 2.42
SOD-123 [mm] "On Semi recommended land pattern"
  rect 0.915x1.22 smd: 1(-1.637,0) 2(1.637,0)
  silkscreen extent -2.74,-1.17 2.03,1.17, body extent -1.93,-0.9 1.93,0.9, height 1.35
SOD-323F [mm] "NXP recommended land pattern"
  rect 0.6x0.6 smd paste-0.05: 1(-1.1,0) 2(1.1,0)
  silkscreen extent -2.13,-0.86 1.53,0.86, body extent -1.35,-0.68 1.35,0.67, height 0.79
SOT1289 [mm] "SMD, 3-Leads, Body 4.3x5.8mm"
  rect 1.6x1.44 smd paste-0.8 mask+0.1: 1(-1.065,2.78) 2(1.065,2.78)
  rect 3.8x4.96 smd paste-2.48 mask+0.1: 3(0,-1.02)
  silkscreen extent -2.65,-2.95 2.2,2.99, body extent -2.2,-2.95 2.2,2.95, height 0.87
SOT-23 [mm] "SOT23, 3-Leads, Body 2.9x1.3mm, Pitch 0.95mm, Lead Span 2.5mm, IPC Medium Density"
  rrect50% 1x0.6 smd: 1(-1.2,0.95) 2(-1.2,-0.95) 3(1.2,0)
  silkscreen extent -1.63,-1.5 0.7,1.5, body extent -1.16,-1.45 1.21,1.45, height 1
Sullins_Gxx02SAAN [mm] "Header, 2.54 mm, 2x1, TH"
  rect 1.55x1.55 hole 1.016: 1(-1.27,0)
  round 1.55 hole 1.016: 2(1.27,0)
  silkscreen extent -2.54,-1.75 2.54,1.27, body extent -2.54,-1.27 2.54,1.27, height 8.38
SULLINS_PEC03DAAN [mm] "SULLINS"
  rect 1.65x1.65 hole 1.016 mask+0: 1(-2.54,-1.27)
  round 1.65 hole 1.016 mask+0: 2(-2.54,1.27) 3(0,-1.27) 4(0,1.27) 5(2.54,-1.27) 6(2.54,1.27)
  silkscreen extent -4.06,-2.79 3.81,2.54, body extent -3.81,-2.54 3.81,2.54, height 8.38
TERM_BLK_ED555-2DS [mil]
  rrect4% 100x100 hole 50: 1(0,0)
  round 100 hole 50: 2(138,0)
  silkscreen extent -93,-161 215,113, body extent -69,-150 207,106, height 323
Testpoint_Keystone_Miniature [mil] "Miniature SMT test point"
  rect 135x70 smd: 1(0,0)
  silkscreen extent -78,-46 78,45, body extent -52,-20 52,20, height 61
TI_Stacked_Overlay_Small [mil]
  silkscreen extent -418,-98 418,98
TI_Symbol_Overlay_Medium [mil]
  silkscreen extent -124,-122 124,120
WCAP-PSLP_630x580 [mm] "SMD, 2-Leads, Dia 6.3mm"
  rect 3.5x1.6 smd: 1(-2.8,0) 2(2.8,0)
  silkscreen extent -3.4,-3.4 3.4,3.4, body extent -3.4,-3.4 3.4,3.4, height 5.81
XAL5030 [mil] "Coilcraft XAL5030 12/12/11"
  rect 46x183 smd: 1(-65,0) 2(65,0)
  silkscreen extent -108,-112 108,112, body extent -108,-112 108,112, height 122
XAL7070 [mm] "COILCRAFT"
  rect 1.63x7.33 smd: 1(-2.285,0) 2(2.285,0)
  silkscreen extent -3.8,-4 3.8,4, body extent -3.8,-4 3.8,4, height 7

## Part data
C1: library part CMP-0007475-4, "CAP, CERM, 2200 pF, 100 V, +/- 10%, X7R, 0603", Cap_Case=0603, Manufacturer=MuRata, Supplier Part Number 1=490-1478-1-ND, TempCo=X7R, Tolerance_%=10%, Value1=Unknown, Value2=100V, ValueDisplayed=2200pF
C3 C4 C5 C6: library part CMP-0009164-2, "CAP, CERM, 10 uF, 50 V, +/- 10%, X7S, AEC-Q200 Grade 1, 1210", Cap_Case=1210_280, Manufacturer=TDK, Supplier Part Number 1=445-7004-1-ND, TempCo=X7S, Tolerance_%=10%, Value1="0.002827 ohm", Value2=50V, ValueDisplayed=10uF
C7: library part CMP-0012273-3, "CAP, Aluminum Polymer, 180 uF, 50 V, +/- 20%, 0.019 ohm, SMD, 2-Leads, Dia 10.5mm, Pin Spacing 8mm SMD", Cap_Case=10x12.7mm, Manufacturer=Nichicon, Supplier Part Number 1=493-13774-1-ND, Tolerance_%=20%, Value1="0.019 ohm", Value2=50V, ValueDisplayed=180uF
C8 C9 C10: "CAP, CERM, 10 µF, 50 V, +/- 10%, X7R, 1210", Cap_Case=1210, Manufacturer=MuRata, Supplier Part Number 1=490-6544-1-ND, TempCo=X7R, Tolerance_%=10, Value1=Unknown, Value2=50V, ValueDisplayed=10µF
C11 C15: "CAP, CERM, 0.1 µF, 100 V, +/- 10%, X7R, 0805", Cap_Case=0805, Manufacturer=Kemet, Supplier Part Number 1=399-3486-1-ND, TempCo=X7R, Tolerance_%=10, Value1="0.064 ohm", Value2=100V, ValueDisplayed=0.1µF
C12 C13 C14 C16: "CAP, CERM, 10 µF, 50 V, +/- 20%, X7R, 1210", Cap_Case=1210, Manufacturer=TDK, Supplier Part Number 1=445-14933-1-ND, TempCo=X7R, Tolerance_%=20, Value1=Unknown, Value2=50V, ValueDisplayed=10µF
C17: library part CMP-0006326-2, "CAP, CERM, 0.1 uF, 50 V, +/- 20%, X7R, AEC-Q200 Grade 1, 0402", Cap_Case=0402, Manufacturer=TDK, Supplier Part Number 1=445-12271-1-ND, TempCo=X7R, Tolerance_%=20%, Value1=Unknown, Value2=50V, ValueDisplayed=0.1uF
C18: library part CMP-0006309-2, "CAP, CERM, 1000 pF, 50 V, +/- 5%, C0G/NP0, AEC-Q200 Grade 1, 0402", Cap_Case=0402, Manufacturer=TDK, Supplier Part Number 1=445-6885-1-ND, TempCo=C0G/NP0, Tolerance_%=5%, Value1=Unknown, Value2=50V, ValueDisplayed=1000pF
C19 C27 C44 C45: library part CMP-0006356-2, "CAP, CERM, 0.1 uF, 50 V, +/- 10%, X7R, AEC-Q200 Grade 1, 0402", Cap_Case=0402, Manufacturer=MuRata, Supplier Part Number 1=490-10672-1-ND, TempCo=X7R, Tolerance_%=10%, Value1=Unknown, Value2=50V, ValueDisplayed=0.1uF
C20: "CAP, CERM, 4.7 µF, 16 V, +/- 10%, X7R, 0805", Cap_Case=0805, Manufacturer=MuRata, Supplier Part Number 1=490-4522-1-ND, TempCo=X7R, Tolerance_%=10, Value1="0.006 ohm", Value2=16V, ValueDisplayed=4.7µF
C21: "CAP, CERM, 2.2 µF, 50 V, +/- 10%, X7R, 0805", Cap_Case=0805, Manufacturer=TDK, Supplier Part Number 1=445-5968-1-ND, TempCo=X7R, Tolerance_%=10, Value1="0.00366 ohm", Value2=50V, ValueDisplayed=2.2µF
C22: library part CMP-0006360-2, "CAP, CERM, 470 pF, 50 V, +/- 10%, X7R, AEC-Q200 Grade 1, 0402", Cap_Case=0402, Manufacturer=MuRata, Supplier Part Number 1=490-4913-1-ND, TempCo=X7R, Tolerance_%=10%, Value1=Unknown, Value2=50V, ValueDisplayed=470pF
C23: library part CMP-0006329-2, "CAP, CERM, 0.033 uF, 50 V, +/- 10%, X7R, AEC-Q200 Grade 1, 0402", Cap_Case=0402, Manufacturer=TDK, Supplier Part Number 1=445-6896-1-ND, TempCo=X7R, Tolerance_%=10%, Value1="0.098477 ohm", Value2=50V, ValueDisplayed=0.033uF
C24 C25 C26: "CAP, CERM, 2.2 µF, 100 V, +/- 10%, X7R, 1206_190", Cap_Case=1206, Manufacturer="Samsung Electro-Mechanics", TempCo=X7R, Tolerance_%=10, Value1=Unknown, Value2=100V, ValueDisplayed=2.2µF
C28: library part CMP-0007098-4, "CAP, CERM, 0.47 uF, 50 V, +/- 20%, X7R, AEC-Q200 Grade 1, 0603", Cap_Case=0603, Manufacturer=TDK, Supplier Part Number 1=445-172476-1-ND, TempCo=X7R, Tolerance_%=20%, Value1=Unknown, Value2=50V, ValueDisplayed=0.47uF
C29: "CAP, CERM, 4.7 µF, 16 V, +/- 10%, X5R, 0603", Cap_Case=0603, Manufacturer=MuRata, TempCo=X5R, Tolerance_%=10, Value1=Unknown, Value2=16V, ValueDisplayed=4.7µF
C30 C34 C46: "CAP, CERM, 0.1 µF, 50 V, +/- 10%, X7R, 0603", Cap_Case=0603, Manufacturer=Kemet, Supplier Part Number 1=399-5089-1-ND, TempCo=X7R, Tolerance_%=10, Value1=Unknown, Value2=50V, ValueDisplayed=0.1µF
C31: library part CMP-0006699-2, "CAP, CERM, 1000 pF, 100 V, +/- 10%, X7R, 0402", Cap_Case=0402, Manufacturer=MuRata, Supplier Part Number 1=GRM155R72A102KA01D-ND, TempCo=X7R, Tolerance_%=10%, Value1=Unknown, Value2=100V, ValueDisplayed=1000pF
C32 C33: "CAP, Aluminum Polymer, 82 µF, 16 V, +/- 20%, 0.03 ohm, D6.3xL5.8mm SMD", Cap_Case=6.3x5.8mm, Manufacturer="Wurth Elektronik", Supplier Part Number 1=732-6424-1-ND, Tolerance_%=20, Value1="0.03 ohm", Value2=16V, ValueDisplayed=82µF
C35 C36: "CAP, CERM, 47 µF, 16 V, +/- 15%, X5R, 1206", Cap_Case=1206, Manufacturer=TDK, Supplier Part Number 1=445-6003-1-ND, TempCo=X5R, Tolerance_%=15, Value1=Unknown, Value2=16V, ValueDisplayed=47µF
C37: library part CMP-0006242-2, "CAP, CERM, 33 pF, 50 V, +/- 5%, C0G/NP0, 0402", Cap_Case=0402, Manufacturer=Kemet, Supplier Part Number 1=399-1017-1-ND, TempCo=C0G/NP0, Tolerance_%=5%, Value1=Unknown, Value2=50V, ValueDisplayed=33pF
C38: library part CMP-0006299-2, "CAP, CERM, 0.068 uF, 50 V, +/- 10%, X7R, 0402", Cap_Case=0402, Manufacturer=TDK, Supplier Part Number 1=445-5930-1-ND, TempCo=X7R, Tolerance_%=10%, Value1="0.05606 ohm", Value2=50V, ValueDisplayed=0.068uF
C39 C41 C42: library part CMP-0006324-2, "CAP, CERM, 0.01 uF, 50 V, +/- 10%, X7R, AEC-Q200 Grade 1, 0402", Cap_Case=0402, Manufacturer=TDK, Supplier Part Number 1=445-6893-1-ND, TempCo=X7R, Tolerance_%=10%, Value1="0.333065 ohm", Value2=50V, ValueDisplayed=0.01uF
C40: library part CMP-0006348-2, "CAP, CERM, 22 pF, 50 V, +/- 5%, C0G/NP0, AEC-Q200 Grade 1, 0402", Cap_Case=0402, Manufacturer=MuRata, Supplier Part Number 1=490-9648-1-ND, TempCo=C0G/NP0, Tolerance_%=5%, Value1=Unknown, Value2=50V, ValueDisplayed=22pF
C43: library part CMP-0006822-4, "CAP, CERM, 100 pF, 50 V, +/- 5%, C0G/NP0, 0603", Cap_Case=0603, Manufacturer="Wurth Elektronik", TempCo=C0G/NP0, Tolerance_%=5%, Value1=Unknown, Value2=50V, ValueDisplayed=100pF
D1: library part DDZ6V2B-7, "Diode, Zener, 6.2 V, 500 mW, AEC-Q101, SOD-123", Manufacturer="Diodes Inc.", Power_W=0.5, Supplier Part Number 1=DDZ6V2BDICT-ND, Value1=0.5W
D3: library part CMP-0028984-1, "Diode, Schottky, 60 V, 10 A, AEC-Q101, CFP15", Manufacturer=Nexperia, Supplier Part Number 1=568-12568-1-ND, Value1=10A, Value2=0.56V
D4: "Diode, Schottky, 60 V, 1 A, SOD-323F", Manufacturer="NXP Semiconductor", Supplier Part Number 1=568-4138-1-ND, Value1=1A, Value2=0.66V
D5: "Diode, Schottky, 70 V, 1 A, SMA", Manufacturer="Diodes Inc.", Supplier Part Number 1=B170-FDICT-ND, Value1=1A, Value2=0.79V
FID1 FID2 FID3: library part CMP-0077181-1, "Fiducial mark.  There is nothing to buy or mount.", Manufacturer=N/A
J5: library part CMP-0054576-1, "Header, 2.54 mm, 2x1, Gold, TH", Manufacturer="Sullins Connector Solutions"
J6: library part CMP-0054552-1, "Header, 100mil, 3x2, Tin, TH", Color=Black, Current_A=3A, Manufacturer="Sullins Connector Solutions", Supplier Part Number 1=S2012E-03-ND, Voltage_V=1.8kV
J7 J8: library part CMP-0074913-1, "Terminal Block, 3.5mm Pitch, 2x1, TH", Color=Grey, Current_A=6A, Manufacturer="On-Shore Technology", Supplier Part Number 1=ED1514-ND, Voltage_V=150V
L1: library part CMP-0061002-1, "Inductor, Shielded, Composite, 330 nH, 19.2 A, 0.0032 ohm, SMD", Manufacturer=Coilcraft, Value1="0.0032 ohm", Value2=19.2A, ValueDisplayed=330nH
L2: library part CMP-0013206-2, "Coupled inductor,  A, 0.017 ohm, SMD", Manufacturer=MuRata, Supplier Part Number 1=490-10979-1-ND
L3: "Inductor, Shielded, Composite, 1.8 µH, 21 A, 0.00405 ohm, SMD", Manufacturer=Coilcraft, Value1="0.00405 ohm", Value2=21A, ValueDisplayed=1.8µH
Logo1 Logo2: library part CMP-0074838-1, "Texas Instrument Corporate Signature"
Logo3: library part CMP-0074847-1, "FCC_disclaimer"
MH1 MH2 MH3 MH4: library part CMP-0078424-2, "PCB Mounting Hole, No Pad", Manufacturer=Any, PartNumber=N/A
NT1 NT2 NT3: "Single point connection between nets."
Q1: library part CMP-0000140-2, "MOSFET, P-CH, -60 V, -30 A, PowerPAK_SO-8L", Alternate Manufacturer=None, Manufacturer=Vishay-Siliconix, Supplier Part Number 1=SQJ461EP-T1-GE3-ND, Value1=0.03, Value2="90 nC"
Q2: library part NVTFS5C670NLWFTAG, "MOSFET N-CH 60V 16A 70A 8WDFN", Alternate Manufacturer=-, Manufacturer="Used in BOM report", Supplier Part Number 1=NVTFS5C670NLWFTAG-ND
Q3 Q4: "MOSFET N-CH 60V 5.6A PPAK 1212-8", Alternate Manufacturer=-, Current - Continuous Drain (Id) @ 25°C="16A (Tc)", Input Capacitance (Ciss) @ Vds="980pF @ 30V", Manufacturer="Vishay Siliconix", Power - Max=62W, Supplier Device Package="PowerPAK® 1212-8", Supplier Part Number=SQ7414AEN-T1-GE3-ND
Q5: library part CMP-0000090-2, "MOSFET, P-CH, -60 V, -1.6 A, SOT-23", Alternate Manufacturer=None, Manufacturer=Vishay-Siliconix, Supplier Part Number 1=SI2309CDS-T1-E3CT-ND, Value1=0.4, Value2="2.7 nC"
Q6: library part CMP-0000488-2, "Transistor, NPN, 60 V, 0.5 A, AEC-Q101, SOT-23", Manufacturer="ON Semiconductor", Supplier Part Number 1=MMBTA05LT1GOSCT-ND, Value1="0.5 A"
R1: "RES, 2.00, 1%, 0.5 W, AEC-Q200 Grade 0, 1210", Manufacturer=Panasonic, Power_W=0.5, Supplier Part Number 1=P17258CT-ND, TempCo="100 ppm/C", Tolerance_%=1, Value1=1%, Value2=0.5W, Value_Code=2R00, ValueDisplayed=2.00
R2: library part CMP-0022204-4, "RES, 20.0 k, 1%, 0.1 W, AEC-Q200 Grade 0, 0603", Manufacturer=Vishay-Dale, Power_W=100mW, Supplier Part Number 1=541-20.0KHCT-ND, TempCo="100 ppm/C", Tolerance_%=1%, Value2=0.1W, Value_Code=20k0, ValueDisplayed=20.0k
R3: library part CMP-0018752-2, "RES, 0.18, 5%, 0.25 W, 1206", Manufacturer=Panasonic, Power_W=250mW, Supplier Part Number 1=P.18PCT-ND, TempCo="250 ppm/C", Tolerance_%=5%, Value2=0.25W, Value_Code=R180, ValueDisplayed=0.18
R4: library part CMP-0022447-4, "RES, 49.9 k, 1%, 0.1 W, AEC-Q200 Grade 0, 0603", Manufacturer=Vishay-Dale, Power_W=100mW, Supplier Part Number 1=541-49.9KHCT-ND, TempCo="100 ppm/C", Tolerance_%=1%, Value2=0.1W, Value_Code=49k9, ValueDisplayed=49.9k
R5: library part CMP-0021990-4, "RES, 100 k, 1%, 0.1 W, AEC-Q200 Grade 0, 0603", Manufacturer=Vishay-Dale, Power_W=100mW, Supplier Part Number 1=541-100KHCT-ND, TempCo="100 ppm/C", Tolerance_%=1%, Value2=0.1W, Value_Code=100k
R6: library part CMP-0026129-1, "RES, 1.00, 1%, 0.063 W, 0402", Manufacturer=Vishay-Dale, Power_W=63mW, Supplier Part Number 1=541-1.00LLCT-ND, TempCo="100 ppm/C", Tolerance_%=1%, Value2=0.063W, Value_Code=1R00, ValueDisplayed=1.00
R7: library part CMP-0015100-2, "RES, 0.005, 1%, 1 W, AEC-Q200 Grade 0, 0508", Manufacturer="Susumu Co Ltd", Power_W=1W, Supplier Part Number 1=754-KRL2012MR005FT1, TempCo="25 ppm/C", Tolerance_%=1%, Value_Code=5L000, ValueDisplayed=0.005
R8: library part CMP-0026404-1, "RES, 49.9, 1%, 0.063 W, 0402", Manufacturer=Vishay-Dale, Power_W=63mW, Supplier Part Number 1=541-49.9LCT-ND, TempCo="100 ppm/C", Tolerance_%=1%, Value2=0.063W, Value_Code=49R9, ValueDisplayed=49.9
R9 R15 R23: library part CMP-0027002-2, "RES, 0, 5%, 0.063 W, 0402", Manufacturer=Rohm, Power_W=63mW, Supplier Part Number 1=RHM0.0JCT-ND, TempCo="500 ppm/C", Tolerance_%=5%, Value2=0.063W, Value_Code=0000, ValueDisplayed=0
R10: library part CMP-0026764-1, "RES, 10.0, 1%, 0.063 W, AEC-Q200 Grade 0, 0402", Manufacturer="Stackpole Electronics Inc", Power_W=63mW, Supplier Part Number 1=RMCF0402JT10R0CT-ND, TempCo="100 ppm/C", Tolerance_%=1%, Value2=0.063W, Value_Code=10R0, ValueDisplayed=10.0
R11: library part CMP-0026411-1, "RES, 4.64 k, 1%, 0.063 W, 0402", Manufacturer=Vishay-Dale, Power_W=63mW, Supplier Part Number 1=541-4.64KLCT-ND, TempCo="100 ppm/C", Tolerance_%=1%, Value2=0.063W, Value_Code=4k64, ValueDisplayed=4.64k
R12: library part CMP-0026621-1, "RES, 9.53 k, 1%, 0.063 W, 0402", Manufacturer=Vishay-Dale, Power_W=63mW, Supplier Part Number 1=541-9.53KLCT-ND, TempCo="100 ppm/C", Tolerance_%=1%, Value2=0.063W, Value_Code=9k53, ValueDisplayed=9.53k
R13: library part CMP-0026225-1, "RES, 29.4 k, 1%, 0.063 W, 0402", Manufacturer=Vishay-Dale, Power_W=63mW, Supplier Part Number 1=541-29.4KLCT-ND, TempCo="100 ppm/C", Tolerance_%=1%, Value2=0.063W, Value_Code=29k4, ValueDisplayed=29.4k
R16: library part CMP-0026994-4, "RES, 10 k, 5%, 0.1 W, AEC-Q200 Grade 0, 0402", Manufacturer=Panasonic, Power_W=100mW, Supplier Part Number 1=P10KJCT-ND, TempCo="200 ppm/C", Tolerance_%=5%, Value2=0.1W, Value_Code=10k0, ValueDisplayed=10k
R17: library part CMP-0026827-2, "RES, 10, 5%, 0.063 W, 0402", Manufacturer=Vishay-Dale, Power_W=63mW, Supplier Part Number 1=541-10JCT-ND, TempCo="200 ppm/C", Tolerance_%=5%, Value2=0.063W, Value_Code=10R0, ValueDisplayed=10
R18 R25: library part CMP-0027002-2, "RES, 0, 5%, 0.063 W, 0402", Manufacturer=Rohm, Power_W=63mW, Supplier Part Number 1=RHM0.0JCT-ND, TempCo="500 ppm/C", Tolerance_%=5%, Value2=0.063W, Value_Code=0000, ValueDisplayed=DNP
R19: "RES, 0, 5%, 0.1 W, 0603", Manufacturer=Vishay-Dale, Power_W=0.1, Supplier Part Number 1=541-0.0GCT-ND, TempCo="200 ppm/C", Tolerance_%=5, Value1=5%, Value2=0.1W, Value_Code=0000, ValueDisplayed=0
R20 R26 R27 R28 R30 R33 R34: library part CMP-0027007-2, "RES, 0, 5%, 0.063 W, AEC-Q200 Grade 0, 0402", Manufacturer="KOA Speer", Power_W=63mW, Supplier Part Number 1=660-RK73Z1ETTP, TempCo=ppm/C, Tolerance_%=5%, Value2=0.063W, Value_Code=0000, ValueDisplayed=0
R22: "RES, 0.01, 1%, 1 W, 0612", Manufacturer="Susumu Co Ltd", Power_W=1, Supplier Part Number 1=PRL1632.010FCT-ND, TempCo="200 ppm/C", Value1=1%, Value2=1W, Value_Code=R010, ValueDisplayed=0.01
R24: "RES, 100 k, 1%, 0.1 W, 0603", Manufacturer=Vishay-Dale, Power_W=0.1, Supplier Part Number 1=541-100KHCT-ND, TempCo="100 ppm/C", Tolerance_%=1, Value1=1%, Value2=0.1W, Value_Code=100k
R29: "RES, 1.0, 5%, 0.5 W, 1206", Manufacturer=Bourns, Power_W=0.5, Supplier Part Number 1=652-CRM1206JW1R0ELF, TempCo="150 ppm/C", Tolerance_%=5, Value1=5%, Value2=0.5W, Value_Code=1R00, ValueDisplayed=1.0
R31: library part CMP-0025959-2, "RES, 10.2 k, 1%, 0.063 W, 0402", Manufacturer=Vishay-Dale, Power_W=63mW, Supplier Part Number 1=541-10.2KLCT-ND, TempCo="100 ppm/C", Tolerance_%=1%, Value2=0.063W, Value_Code=10k2, ValueDisplayed=10.2k
R32: library part CMP-0026702-1, "RES, 49.9 k, 1%, 0.1 W, AEC-Q200 Grade 0, 0402", Manufacturer=Panasonic, Power_W=100mW, Supplier Part Number 1=P49.9KLCT-ND, TempCo="100 ppm/C", Tolerance_%=1%, Value2=0.1W, Value_Code=49k9, ValueDisplayed=49.9k
R35: library part CMP-0027007-2, "RES, 0, 5%, 0.063 W, AEC-Q200 Grade 0, 0402", Manufacturer="KOA Speer", PartNumber=RK73Z1ETTP, Power_W=63mW, Supplier Part Number 1=660-RK73Z1ETTP, TempCo=ppm/C, Tolerance_%=5%, Value2=0.063W, Value_Code=0000
R36 R37: library part CMP-0022986-3, "RES, 2.20 k, 1%, 0.1 W, 0603", Manufacturer="Yageo America", Power_W=100mW, Supplier Part Number 1=311-2.20KHRCT-ND, TempCo="200 ppm/C", Tolerance_%=1%, Value2=0.1W, Value_Code=2k20, ValueDisplayed=2.20k
TP1 TP7: "Test Point, Miniature, SMT", Manufacturer=Keystone, Supplier Part Number 1=36-5015TR-ND
TP4: "Test Point, Miniature, White, TH", Color=White, Manufacturer=Keystone, Supplier Part Number 1=36-5002-ND
TP5 TP6: "Test Point, Miniature, White, TH", Manufacturer=Keystone, Supplier Part Number 1=5002K-ND
U1: library part CMP-0014055-4, "Wide VIN Automotive Low IQ Boost Controller, RUM0016C (WQFN-16)", Alternate Manufacturer="Texas Instruments", Alternate PartNumber=LM5150QRUMTQ1
U2: "Wide Input 2.2MHz low Iq Synchronous Buck Controller, RGE0024J (VQFN-24)", Alternate Manufacturer="Texas Instruments"
U4: library part CMP-0068899-1, "CMOS Timer, 8-pin Mini SOIC", Manufacturer="Texas Instruments", PackageTopMarking=ZXTT*ZC5, PowerWise=N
